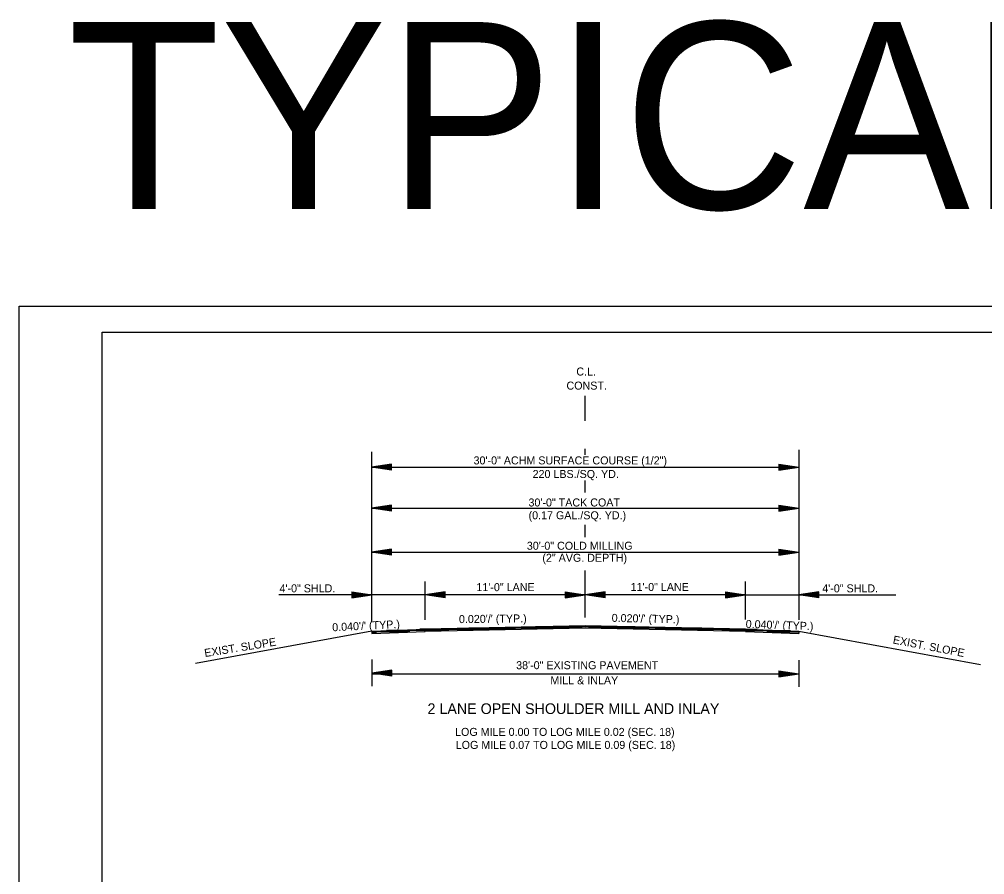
# Model space of a CAD drawing. Extents: x 2263886 to 2266026, y -3122850 to -3121850.
# Drawn here: x 2265192.4 to 2265264.7, y -3122379.7 to -3122315.7 of the extents above; entities that cross this region are included whole.
import ezdxf

# ---------------------------------------------------------------- set-up
doc = ezdxf.new("R2010")
doc.units = 0
for name, color, linetype in [('_CIVIL_CONSTRUCTION', 7, 'Continuous'), ('Default', 7, 'Continuous'), ('R_Border Prem', 7, 'Continuous'), ('R_Draft', 7, 'Continuous')]:
    doc.layers.add(name, color=color, linetype=linetype)

msp = doc.modelspace()

# ---------------------------------------------------------------- linework, layer by layer
at = {"layer": '_CIVIL_CONSTRUCTION'}
msp.add_line((2265192.355, -3122337.151), (2265359.022, -3122337.151), dxfattribs=at)
for points in [[(2265192.352, -3122337.151), (2265359.022, -3122337.151), (2265359.022, -3122443.82), (2265192.352, -3122443.82)], [(2265315.516, -3122339.098), (2265315.516, -3122344.038), (2265333.382, -3122344.038), (2265333.382, -3122345.498), (2265344.981, -3122345.498), (2265344.981, -3122357.664), (2265356.646, -3122357.664), (2265356.646, -3122441.828), (2265198.556, -3122441.828), (2265198.556, -3122339.098)]]:
    msp.add_lwpolyline(points, close=True, dxfattribs=at)
at = {"layer": 'Default'}
for p, q in [((2265238.501, -3122361.176), (2265231.036, -3122361.176)), ((2265221.63, -3122361.556), (2265218.773, -3122361.556)), ((2265219.132, -3122361.656), (2265218.777, -3122361.656)), ((2265222.767, -3122361.456), (2265219.879, -3122361.456)), ((2265222.767, -3122361.356), (2265222.379, -3122361.356)), ((2265229.536, -3122361.376), (2265222.767, -3122361.376)), ((2265224.536, -3122361.476), (2265222.767, -3122361.476)), ((2265234.537, -3122361.276), (2265226.036, -3122361.276)), ((2265243.501, -3122361.276), (2265235.006, -3122361.276)), ((2265246.788, -3122361.376), (2265240.003, -3122361.376)), ((2265246.786, -3122361.476), (2265245, -3122361.476)), ((2265250.145, -3122361.476), (2265246.786, -3122361.476)), ((2265247.645, -3122361.376), (2265246.788, -3122361.376)), ((2265250.782, -3122361.576), (2265248.392, -3122361.576))]:
    msp.add_line(p, q, dxfattribs=at)
at = {"layer": 'R_Border Prem'}
for p, q in [((2265234.768, -3122344.303), (2265234.768, -3122343.862)), ((2265234.768, -3122345.726), (2265234.768, -3122344.082)), ((2265218.742, -3122348.063), (2265218.742, -3122360.817)), ((2265234.768, -3122348.286), (2265234.768, -3122347.825)), ((2265220.242, -3122348.976), (2265218.742, -3122349.201)), ((2265218.742, -3122349.201), (2265250.782, -3122349.201)), ((2265220.242, -3122349.426), (2265218.742, -3122349.201)), ((2265220.242, -3122349.013), (2265218.993, -3122349.201)), ((2265220.242, -3122349.388), (2265218.993, -3122349.201)), ((2265220.242, -3122349.052), (2265219.251, -3122349.201)), ((2265220.242, -3122349.35), (2265219.251, -3122349.201)), ((2265220.242, -3122349.089), (2265219.5, -3122349.201)), ((2265220.242, -3122349.313), (2265219.5, -3122349.201)), ((2265220.242, -3122349.127), (2265219.755, -3122349.201)), ((2265220.242, -3122349.274), (2265219.755, -3122349.201)), ((2265220.242, -3122349.166), (2265220.005, -3122349.201)), ((2265220.242, -3122349.236), (2265220.005, -3122349.201)), ((2265220.242, -3122349.426), (2265220.242, -3122348.976)), ((2265249.282, -3122348.976), (2265250.782, -3122349.201)), ((2265249.282, -3122348.976), (2265249.282, -3122349.426)), ((2265249.282, -3122349.013), (2265250.531, -3122349.201)), ((2265249.282, -3122349.052), (2265250.273, -3122349.201)), ((2265249.282, -3122349.089), (2265250.023, -3122349.201)), ((2265249.282, -3122349.128), (2265249.769, -3122349.201)), ((2265249.282, -3122349.166), (2265249.519, -3122349.201)), ((2265249.282, -3122349.426), (2265250.782, -3122349.201)), ((2265249.282, -3122349.274), (2265249.769, -3122349.201)), ((2265249.282, -3122349.35), (2265250.273, -3122349.201)), ((2265249.282, -3122349.388), (2265250.531, -3122349.201)), ((2265249.282, -3122349.313), (2265250.023, -3122349.201)), ((2265249.282, -3122349.236), (2265249.519, -3122349.201)), ((2265234.768, -3122351.116), (2265234.768, -3122350.2)), ((2265220.242, -3122352.063), (2265218.742, -3122352.288)), ((2265218.742, -3122352.288), (2265250.782, -3122352.288)), ((2265220.242, -3122352.513), (2265218.742, -3122352.288)), ((2265220.242, -3122352.1), (2265218.993, -3122352.288)), ((2265220.242, -3122352.475), (2265218.993, -3122352.288)), ((2265220.242, -3122352.139), (2265219.251, -3122352.288)), ((2265220.242, -3122352.437), (2265219.251, -3122352.288)), ((2265220.242, -3122352.176), (2265219.5, -3122352.288)), ((2265220.242, -3122352.4), (2265219.5, -3122352.288)), ((2265220.242, -3122352.214), (2265219.755, -3122352.288)), ((2265220.242, -3122352.361), (2265219.755, -3122352.288)), ((2265220.242, -3122352.253), (2265220.005, -3122352.288)), ((2265220.242, -3122352.323), (2265220.005, -3122352.288)), ((2265220.242, -3122352.513), (2265220.242, -3122352.063)), ((2265249.282, -3122352.063), (2265250.782, -3122352.288)), ((2265249.282, -3122352.063), (2265249.282, -3122352.513)), ((2265249.282, -3122352.1), (2265250.531, -3122352.288)), ((2265249.282, -3122352.139), (2265250.273, -3122352.288)), ((2265249.282, -3122352.176), (2265250.023, -3122352.288)), ((2265249.282, -3122352.215), (2265249.769, -3122352.288)), ((2265249.282, -3122352.253), (2265249.519, -3122352.288)), ((2265249.282, -3122352.513), (2265250.782, -3122352.288)), ((2265249.282, -3122352.361), (2265249.769, -3122352.288)), ((2265249.282, -3122352.437), (2265250.273, -3122352.288)), ((2265249.282, -3122352.475), (2265250.531, -3122352.288)), ((2265249.282, -3122352.4), (2265250.023, -3122352.288)), ((2265249.282, -3122352.323), (2265249.519, -3122352.288)), ((2265234.768, -3122354.452), (2265234.768, -3122353.521)), ((2265220.242, -3122355.356), (2265218.742, -3122355.581)), ((2265220.242, -3122355.393), (2265218.993, -3122355.581)), ((2265220.242, -3122355.432), (2265219.251, -3122355.581)), ((2265220.242, -3122355.806), (2265220.242, -3122355.356)), ((2265249.282, -3122355.356), (2265250.782, -3122355.581)), ((2265249.282, -3122355.356), (2265249.282, -3122355.806)), ((2265249.282, -3122355.393), (2265250.531, -3122355.581)), ((2265249.282, -3122355.432), (2265250.273, -3122355.581)), ((2265218.742, -3122355.581), (2265250.782, -3122355.581)), ((2265220.242, -3122355.806), (2265218.742, -3122355.581)), ((2265220.242, -3122355.768), (2265218.993, -3122355.581)), ((2265220.242, -3122355.73), (2265219.251, -3122355.581)), ((2265220.242, -3122355.469), (2265219.5, -3122355.581)), ((2265220.242, -3122355.693), (2265219.5, -3122355.581)), ((2265220.242, -3122355.507), (2265219.755, -3122355.581)), ((2265220.242, -3122355.654), (2265219.755, -3122355.581)), ((2265220.242, -3122355.546), (2265220.005, -3122355.581)), ((2265220.242, -3122355.616), (2265220.005, -3122355.581)), ((2265249.282, -3122355.469), (2265250.023, -3122355.581)), ((2265249.282, -3122355.508), (2265249.769, -3122355.581)), ((2265249.282, -3122355.546), (2265249.519, -3122355.581)), ((2265249.282, -3122355.806), (2265250.782, -3122355.581)), ((2265249.282, -3122355.654), (2265249.769, -3122355.581)), ((2265249.282, -3122355.73), (2265250.273, -3122355.581)), ((2265249.282, -3122355.768), (2265250.531, -3122355.581)), ((2265249.282, -3122355.693), (2265250.023, -3122355.581)), ((2265249.282, -3122355.616), (2265249.519, -3122355.581)), ((2265234.768, -3122358.767), (2265234.768, -3122356.958)), ((2265222.767, -3122360.633), (2265222.767, -3122357.778)), ((2265246.788, -3122360.632), (2265246.788, -3122357.777)), ((2265222.767, -3122358.784), (2265211.809, -3122358.784)), ((2265217.267, -3122358.559), (2265218.767, -3122358.784)), ((2265217.267, -3122358.559), (2265217.267, -3122359.009)), ((2265217.267, -3122358.597), (2265218.517, -3122358.784)), ((2265217.267, -3122358.635), (2265218.259, -3122358.784)), ((2265217.267, -3122358.672), (2265218.009, -3122358.784)), ((2265217.267, -3122358.711), (2265217.755, -3122358.784)), ((2265217.267, -3122358.749), (2265217.504, -3122358.784)), ((2265217.267, -3122359.009), (2265218.767, -3122358.784)), ((2265217.267, -3122358.858), (2265217.755, -3122358.784)), ((2265217.267, -3122358.933), (2265218.259, -3122358.784)), ((2265217.267, -3122358.972), (2265218.517, -3122358.784)), ((2265217.267, -3122358.896), (2265218.009, -3122358.784)), ((2265217.267, -3122358.819), (2265217.504, -3122358.784)), ((2265224.267, -3122358.542), (2265222.767, -3122358.767)), ((2265234.767, -3122358.767), (2265222.767, -3122358.767)), ((2265224.267, -3122358.992), (2265222.767, -3122358.767)), ((2265224.267, -3122358.579), (2265223.018, -3122358.767)), ((2265224.267, -3122358.954), (2265223.018, -3122358.767)), ((2265224.267, -3122358.618), (2265223.276, -3122358.767)), ((2265224.267, -3122358.916), (2265223.276, -3122358.767)), ((2265224.267, -3122358.655), (2265223.525, -3122358.767)), ((2265224.267, -3122358.879), (2265223.525, -3122358.767)), ((2265224.267, -3122358.693), (2265223.78, -3122358.767)), ((2265224.267, -3122358.84), (2265223.78, -3122358.767)), ((2265224.267, -3122358.732), (2265224.03, -3122358.767)), ((2265224.267, -3122358.802), (2265224.03, -3122358.767)), ((2265224.267, -3122358.992), (2265224.267, -3122358.542)), ((2265233.262, -3122358.542), (2265234.762, -3122358.767)), ((2265233.262, -3122358.542), (2265233.262, -3122358.992)), ((2265233.262, -3122358.579), (2265234.512, -3122358.767)), ((2265233.262, -3122358.618), (2265234.254, -3122358.767)), ((2265233.262, -3122358.655), (2265234.004, -3122358.767)), ((2265233.262, -3122358.694), (2265233.75, -3122358.767)), ((2265233.262, -3122358.732), (2265233.499, -3122358.767)), ((2265233.262, -3122358.992), (2265234.762, -3122358.767)), ((2265233.262, -3122358.84), (2265233.75, -3122358.767)), ((2265233.262, -3122358.916), (2265234.254, -3122358.767)), ((2265233.262, -3122358.954), (2265234.512, -3122358.767)), ((2265233.262, -3122358.879), (2265234.004, -3122358.767)), ((2265233.262, -3122358.802), (2265233.499, -3122358.767)), ((2265236.262, -3122358.542), (2265234.762, -3122358.767)), ((2265246.788, -3122358.767), (2265234.762, -3122358.767)), ((2265236.262, -3122358.992), (2265234.762, -3122358.767)), ((2265234.768, -3122360.475), (2265234.768, -3122358.786)), ((2265236.262, -3122358.579), (2265235.013, -3122358.767)), ((2265236.262, -3122358.954), (2265235.013, -3122358.767)), ((2265236.262, -3122358.618), (2265235.271, -3122358.767)), ((2265236.262, -3122358.916), (2265235.271, -3122358.767)), ((2265236.262, -3122358.655), (2265235.52, -3122358.767)), ((2265236.262, -3122358.879), (2265235.52, -3122358.767)), ((2265236.262, -3122358.693), (2265235.775, -3122358.767)), ((2265236.262, -3122358.84), (2265235.775, -3122358.767)), ((2265236.262, -3122358.732), (2265236.025, -3122358.767)), ((2265236.262, -3122358.802), (2265236.025, -3122358.767)), ((2265236.262, -3122358.992), (2265236.262, -3122358.542)), ((2265245.288, -3122358.542), (2265246.788, -3122358.767)), ((2265245.288, -3122358.542), (2265245.288, -3122358.992)), ((2265245.288, -3122358.579), (2265246.538, -3122358.767)), ((2265245.288, -3122358.618), (2265246.28, -3122358.767)), ((2265245.288, -3122358.655), (2265246.03, -3122358.767)), ((2265245.288, -3122358.694), (2265245.776, -3122358.767)), ((2265245.288, -3122358.732), (2265245.525, -3122358.767)), ((2265245.288, -3122358.992), (2265246.788, -3122358.767)), ((2265245.288, -3122358.84), (2265245.776, -3122358.767)), ((2265245.288, -3122358.916), (2265246.28, -3122358.767)), ((2265245.288, -3122358.954), (2265246.538, -3122358.767)), ((2265245.288, -3122358.879), (2265246.03, -3122358.767)), ((2265245.288, -3122358.802), (2265245.525, -3122358.767)), ((2265246.788, -3122358.767), (2265258.062, -3122358.767)), ((2265252.288, -3122358.542), (2265250.788, -3122358.767)), ((2265252.288, -3122358.992), (2265250.788, -3122358.767)), ((2265252.288, -3122358.579), (2265251.039, -3122358.767)), ((2265252.288, -3122358.954), (2265251.039, -3122358.767)), ((2265252.288, -3122358.618), (2265251.297, -3122358.767)), ((2265252.288, -3122358.916), (2265251.297, -3122358.767)), ((2265252.288, -3122358.655), (2265251.547, -3122358.767)), ((2265252.288, -3122358.879), (2265251.547, -3122358.767)), ((2265252.288, -3122358.693), (2265251.801, -3122358.767)), ((2265252.288, -3122358.84), (2265251.801, -3122358.767)), ((2265252.288, -3122358.732), (2265252.051, -3122358.767)), ((2265252.288, -3122358.802), (2265252.051, -3122358.767)), ((2265252.288, -3122358.992), (2265252.288, -3122358.542)), ((2265234.768, -3122361.101), (2265222.767, -3122361.341)), ((2265246.788, -3122361.341), (2265234.768, -3122361.101)), ((2265218.777, -3122361.5), (2265205.553, -3122363.929)), ((2265218.77, -3122361.501), (2265222.767, -3122361.341)), ((2265218.777, -3122361.501), (2265218.777, -3122361.671)), ((2265218.777, -3122361.671), (2265222.774, -3122361.511)), ((2265222.767, -3122361.511), (2265222.767, -3122361.341)), ((2265234.772, -3122361.271), (2265222.771, -3122361.511)), ((2265246.785, -3122361.511), (2265234.765, -3122361.271)), ((2265246.782, -3122361.511), (2265250.778, -3122361.671)), ((2265246.788, -3122361.341), (2265250.785, -3122361.501)), ((2265246.788, -3122361.341), (2265246.788, -3122361.511)), ((2265250.778, -3122361.501), (2265250.778, -3122361.671)), ((2265250.778, -3122361.501), (2265264.398, -3122364.002)), ((2265218.777, -3122363.618), (2265218.777, -3122365.618)), ((2265250.778, -3122363.656), (2265250.778, -3122365.656)), ((2265220.277, -3122364.418), (2265218.777, -3122364.643)), ((2265220.277, -3122364.868), (2265218.777, -3122364.643)), ((2265218.777, -3122364.681), (2265250.778, -3122364.681)), ((2265220.277, -3122364.456), (2265219.028, -3122364.643)), ((2265220.277, -3122364.831), (2265219.028, -3122364.643)), ((2265220.277, -3122364.494), (2265219.286, -3122364.643)), ((2265220.277, -3122364.793), (2265219.286, -3122364.643)), ((2265220.277, -3122364.532), (2265219.535, -3122364.643)), ((2265220.277, -3122364.755), (2265219.535, -3122364.643)), ((2265220.277, -3122364.57), (2265219.79, -3122364.643)), ((2265220.277, -3122364.716), (2265219.79, -3122364.643)), ((2265220.277, -3122364.608), (2265220.04, -3122364.643)), ((2265220.277, -3122364.679), (2265220.04, -3122364.643)), ((2265220.277, -3122364.868), (2265220.277, -3122364.418)), ((2265249.278, -3122364.456), (2265250.778, -3122364.681)), ((2265249.278, -3122364.456), (2265249.278, -3122364.906)), ((2265249.278, -3122364.493), (2265250.528, -3122364.681)), ((2265249.278, -3122364.532), (2265250.27, -3122364.681)), ((2265249.278, -3122364.569), (2265250.02, -3122364.681)), ((2265249.278, -3122364.608), (2265249.766, -3122364.681)), ((2265249.278, -3122364.646), (2265249.515, -3122364.681)), ((2265249.278, -3122364.906), (2265250.778, -3122364.681)), ((2265249.278, -3122364.754), (2265249.766, -3122364.681)), ((2265249.278, -3122364.83), (2265250.27, -3122364.681)), ((2265249.278, -3122364.868), (2265250.528, -3122364.681)), ((2265249.278, -3122364.793), (2265250.02, -3122364.681)), ((2265249.278, -3122364.716), (2265249.515, -3122364.681))]:
    msp.add_line(p, q, dxfattribs=at)
msp.add_lwpolyline([(2265250.782, -3122347.9), (2265250.782, -3122360.638)], dxfattribs=at)
at = {"layer": 'R_Draft'}
for p, q in [((2265198.556, -3122339.098), (2265356.646, -3122339.098)), ((2265198.556, -3122441.828), (2265198.556, -3122339.098))]:
    msp.add_line(p, q, dxfattribs=at)

# ---------------------------------------------------------------- texts
at = {"layer": 'R_Border Prem'}
for s, height, p in [('TYPICALS FOR PLANS', 14, (2265195.983, -3122329.865)), ('C.L.', 0.6, (2265234.101, -3122342.342)), ('CONST.', 0.6, (2265233.364, -3122343.398)), ('30\'-0" ACHM SURFACE COURSE (1/2")', 0.6, (2265226.4, -3122349.001)), ('220 LBS./SQ. YD. ', 0.6, (2265230.824, -3122350.02)), ('30\'-0" TACK COAT', 0.6, (2265230.515, -3122352.153)), ('(0.17 GAL./SQ. YD.)', 0.6, (2265230.523, -3122353.113)), ('30\'-0" COLD MILLING', 0.6, (2265230.392, -3122355.395)), ('(2" AVG. DEPTH)', 0.6, (2265231.556, -3122356.295)), ('4\'-0" SHLD.', 0.6, (2265211.854, -3122358.585)), ('11\'-0" LANE', 0.6, (2265226.612, -3122358.496)), ('11\'-0" LANE', 0.6, (2265238.171, -3122358.484)), ('4\'-0" SHLD.', 0.6, (2265252.535, -3122358.588)), ('38\'-0" EXISTING PAVEMENT', 0.6, (2265229.591, -3122364.346)), ('MILL & INLAY', 0.6, (2265232.157, -3122365.48)), ('2 LANE OPEN SHOULDER MILL AND INLAY', 0.8, (2265222.947, -3122367.701)), ('LOG MILE 0.00 TO LOG MILE 0.02 (SEC. 18)', 0.6, (2265225.015, -3122369.341)), ('LOG MILE 0.07 TO LOG MILE 0.09 (SEC. 18)', 0.6, (2265225.062, -3122370.316))]:
    msp.add_text(s, height=height, dxfattribs=at).set_placement(p)
for s, rotation, p in [("0.020'/' (TYP.)", 0.6486, (2265225.307, -3122360.892)), ("0.020'/' (TYP.)", 358.70131, (2265236.747, -3122360.796)), ("0.040'/' (TYP.)", 2.84007, (2265215.819, -3122361.508)), ("0.040'/' (TYP.)", 358.01958, (2265246.789, -3122361.247)), ('EXIST. SLOPE', 349.11714, (2265257.793, -3122362.409)), ('EXIST. SLOPE', 9.15344, (2265206.27, -3122363.435))]:
    msp.add_text(s, height=0.6, rotation=rotation, dxfattribs=at).set_placement(p)

doc.saveas('drawing.dxf')
